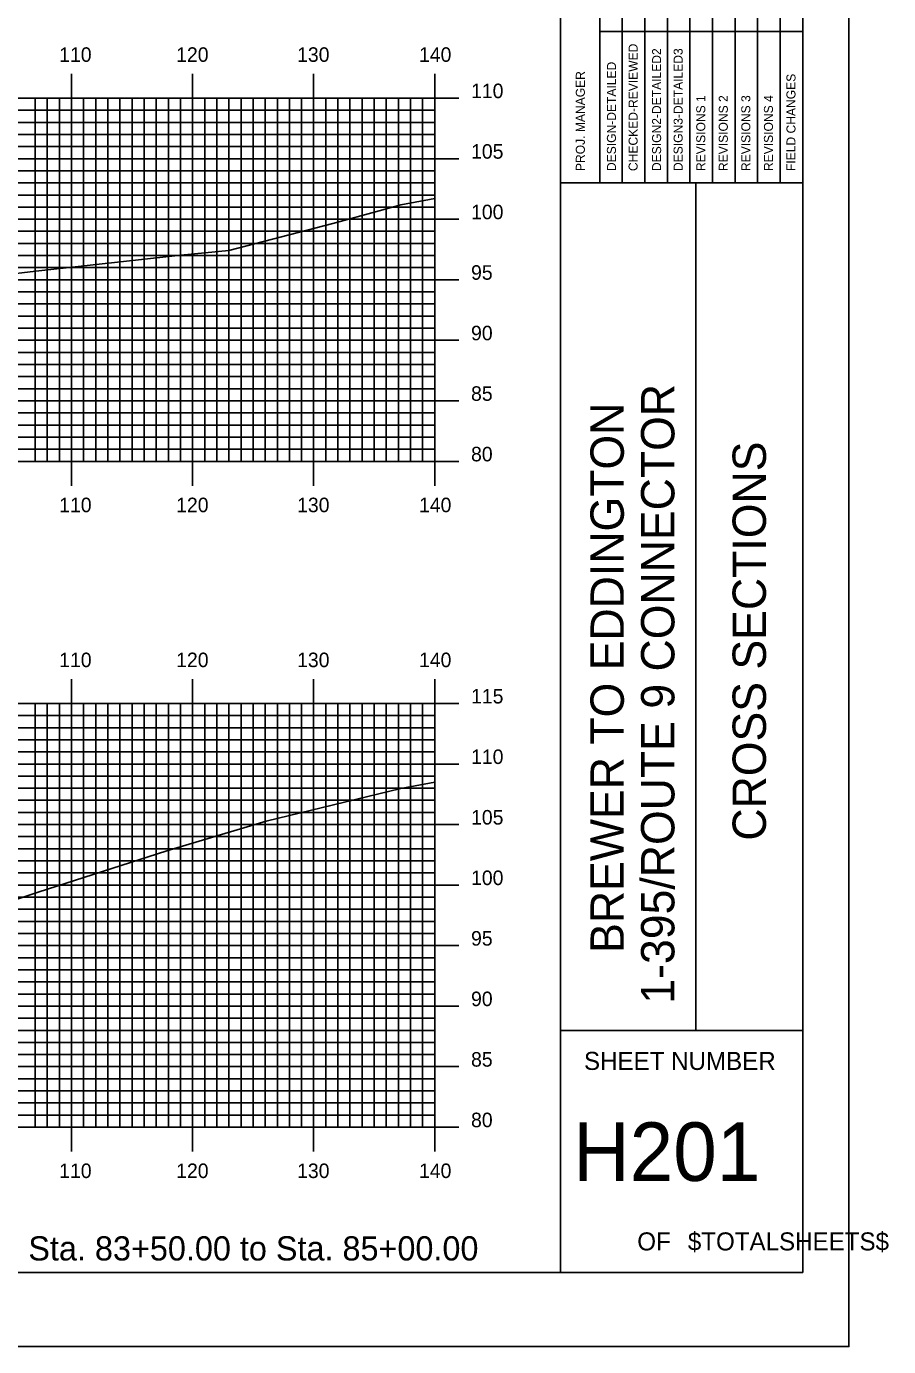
# Model space of a CAD drawing. Extents: x 1763365 to 1763708, y 442591 to 442811.
# Drawn here: x 1763637.1 to 1763708.3, y 442590.5 to 442699.6 of the extents above; entities that cross this region are included whole.
import ezdxf

# ---------------------------------------------------------------- set-up
doc = ezdxf.new("R2010")
doc.units = 0
for name, color, linetype in [('BORDER', 7, 'Continuous'), ('H_V ANNOTATION', 7, 'Continuous'), ('MAJOR', 7, 'Continuous'), ('MINOR', 7, 'Continuous'), ('PLOT BOUNDARY', 7, 'Continuous'), ('S_Roadway_Centerline', 7, 'Continuous')]:
    doc.layers.add(name, color=color, linetype=linetype)

msp = doc.modelspace()

# ---------------------------------------------------------------- linework, layer by layer
at = {"layer": 'BORDER'}
for p, q in [((1763681.21, 442596.67), (1763681.21, 442806.67)), ((1763681.21, 442686.67), (1763701.21, 442686.67)), ((1763692.39, 442616.67), (1763692.39, 442686.67)), ((1763681.21, 442616.67), (1763701.21, 442616.67))]:
    msp.add_line(p, q, dxfattribs=at)
msp.add_lwpolyline([(1763381.21, 442596.67), (1763701.21, 442596.67), (1763701.21, 442806.67), (1763381.21, 442806.67)], close=True, dxfattribs=at)
for points in [[(1763686.3, 442686.68), (1763686.3, 442721.67)], [(1763688.16, 442721.67), (1763688.16, 442686.68)], [(1763690.03, 442686.68), (1763690.03, 442721.67)], [(1763691.89, 442686.68), (1763691.89, 442721.67)], [(1763693.75, 442686.68), (1763693.75, 442721.67)], [(1763695.62, 442686.68), (1763695.62, 442721.67)], [(1763697.48, 442686.68), (1763697.48, 442721.67)], [(1763699.34, 442686.68), (1763699.34, 442721.67)], [(1763684.44, 442686.68), (1763684.44, 442720.26)], [(1763684.44, 442699.17), (1763701.21, 442699.17)]]:
    msp.add_lwpolyline(points, dxfattribs=at)
at = {"layer": 'MAJOR'}
for p, q in [((1763640.81, 442695.67), (1763640.81, 442693.67)), ((1763650.81, 442695.67), (1763650.81, 442693.67)), ((1763660.81, 442695.67), (1763660.81, 442693.67)), ((1763670.81, 442695.67), (1763670.81, 442693.67)), ((1763390.81, 442693.67), (1763670.81, 442693.67)), ((1763390.81, 442693.67), (1763670.81, 442693.67)), ((1763640.81, 442663.67), (1763640.81, 442693.67)), ((1763650.81, 442663.67), (1763650.81, 442693.67)), ((1763660.81, 442663.67), (1763660.81, 442693.67)), ((1763672.81, 442693.67), (1763668.8, 442693.67)), ((1763670.81, 442663.67), (1763670.81, 442693.67)), ((1763670.81, 442663.67), (1763670.81, 442693.67)), ((1763390.81, 442688.67), (1763670.81, 442688.67)), ((1763672.81, 442688.67), (1763668.8, 442688.67)), ((1763390.81, 442683.67), (1763670.81, 442683.67)), ((1763672.81, 442683.67), (1763668.8, 442683.67)), ((1763390.81, 442678.67), (1763670.81, 442678.67)), ((1763672.81, 442678.67), (1763668.8, 442678.67)), ((1763390.81, 442673.67), (1763670.81, 442673.67)), ((1763672.81, 442673.67), (1763668.8, 442673.67)), ((1763390.81, 442668.67), (1763670.81, 442668.67)), ((1763672.81, 442668.67), (1763668.8, 442668.67)), ((1763390.81, 442663.67), (1763670.81, 442663.67)), ((1763390.81, 442663.67), (1763670.81, 442663.67)), ((1763640.81, 442661.66), (1763640.81, 442663.67)), ((1763650.81, 442661.66), (1763650.81, 442663.67)), ((1763660.81, 442661.66), (1763660.81, 442663.67)), ((1763672.81, 442663.67), (1763668.8, 442663.67)), ((1763670.81, 442661.66), (1763670.81, 442663.67)), ((1763640.81, 442645.67), (1763640.81, 442643.67)), ((1763650.81, 442645.67), (1763650.81, 442643.67)), ((1763660.81, 442645.67), (1763660.81, 442643.67)), ((1763670.81, 442645.67), (1763670.81, 442643.67)), ((1763390.81, 442643.67), (1763670.81, 442643.67)), ((1763390.81, 442643.67), (1763670.81, 442643.67)), ((1763640.81, 442608.67), (1763640.81, 442643.67)), ((1763650.81, 442608.67), (1763650.81, 442643.67)), ((1763660.81, 442608.67), (1763660.81, 442643.67)), ((1763672.81, 442643.67), (1763668.8, 442643.67)), ((1763670.81, 442608.67), (1763670.81, 442643.67)), ((1763670.81, 442608.67), (1763670.81, 442643.67)), ((1763390.81, 442638.67), (1763670.81, 442638.67)), ((1763672.81, 442638.67), (1763668.8, 442638.67)), ((1763390.81, 442633.67), (1763670.81, 442633.67)), ((1763672.81, 442633.67), (1763668.8, 442633.67)), ((1763390.81, 442628.67), (1763670.81, 442628.67)), ((1763672.81, 442628.67), (1763668.8, 442628.67)), ((1763390.81, 442623.67), (1763670.81, 442623.67)), ((1763672.81, 442623.67), (1763668.8, 442623.67)), ((1763390.81, 442618.67), (1763670.81, 442618.67)), ((1763672.81, 442618.67), (1763668.8, 442618.67)), ((1763390.81, 442613.67), (1763670.81, 442613.67)), ((1763672.81, 442613.67), (1763668.8, 442613.67)), ((1763390.81, 442608.67), (1763670.81, 442608.67)), ((1763390.81, 442608.67), (1763670.81, 442608.67)), ((1763640.81, 442606.66), (1763640.81, 442608.67)), ((1763650.81, 442606.66), (1763650.81, 442608.67)), ((1763660.81, 442606.66), (1763660.81, 442608.67)), ((1763672.81, 442608.67), (1763668.8, 442608.67)), ((1763670.81, 442606.66), (1763670.81, 442608.67))]:
    msp.add_line(p, q, dxfattribs=at)
at = {"layer": 'MINOR'}
for p, q in [((1763637.81, 442663.67), (1763637.81, 442693.67)), ((1763638.81, 442663.67), (1763638.81, 442693.67)), ((1763639.81, 442663.67), (1763639.81, 442693.67)), ((1763641.81, 442663.67), (1763641.81, 442693.67)), ((1763642.81, 442663.67), (1763642.81, 442693.67)), ((1763643.81, 442663.67), (1763643.81, 442693.67)), ((1763644.81, 442663.67), (1763644.81, 442693.67)), ((1763645.81, 442663.67), (1763645.81, 442693.67)), ((1763646.81, 442663.67), (1763646.81, 442693.67)), ((1763647.81, 442663.67), (1763647.81, 442693.67)), ((1763648.81, 442663.67), (1763648.81, 442693.67)), ((1763649.81, 442663.67), (1763649.81, 442693.67)), ((1763651.81, 442663.67), (1763651.81, 442693.67)), ((1763652.81, 442663.67), (1763652.81, 442693.67)), ((1763653.81, 442663.67), (1763653.81, 442693.67)), ((1763654.81, 442663.67), (1763654.81, 442693.67)), ((1763655.81, 442663.67), (1763655.81, 442693.67)), ((1763656.81, 442663.67), (1763656.81, 442693.67)), ((1763657.81, 442663.67), (1763657.81, 442693.67)), ((1763658.81, 442663.67), (1763658.81, 442693.67)), ((1763659.81, 442663.67), (1763659.81, 442693.67)), ((1763661.81, 442663.67), (1763661.81, 442693.67)), ((1763662.81, 442663.67), (1763662.81, 442693.67)), ((1763663.81, 442663.67), (1763663.81, 442693.67)), ((1763664.81, 442663.67), (1763664.81, 442693.67)), ((1763665.81, 442663.67), (1763665.81, 442693.67)), ((1763666.81, 442663.67), (1763666.81, 442693.67)), ((1763667.81, 442663.67), (1763667.81, 442693.67)), ((1763668.81, 442663.67), (1763668.81, 442693.67)), ((1763669.81, 442663.67), (1763669.81, 442693.67)), ((1763390.81, 442692.67), (1763670.81, 442692.67)), ((1763390.81, 442691.67), (1763670.81, 442691.67)), ((1763670.81, 442692.67), (1763668.8, 442692.67)), ((1763670.81, 442691.67), (1763668.8, 442691.67)), ((1763390.81, 442690.67), (1763670.81, 442690.67)), ((1763670.81, 442690.67), (1763668.8, 442690.67)), ((1763390.81, 442689.67), (1763670.81, 442689.67)), ((1763670.81, 442689.67), (1763668.8, 442689.67)), ((1763390.81, 442687.67), (1763670.81, 442687.67)), ((1763670.81, 442687.67), (1763668.8, 442687.67)), ((1763390.81, 442686.67), (1763670.81, 442686.67)), ((1763670.81, 442686.67), (1763668.8, 442686.67)), ((1763390.81, 442685.67), (1763670.81, 442685.67)), ((1763670.81, 442685.67), (1763668.8, 442685.67)), ((1763390.81, 442684.67), (1763670.81, 442684.67)), ((1763670.81, 442684.67), (1763668.8, 442684.67)), ((1763390.81, 442682.67), (1763670.81, 442682.67)), ((1763670.81, 442682.67), (1763668.8, 442682.67)), ((1763390.81, 442681.67), (1763670.81, 442681.67)), ((1763670.81, 442681.67), (1763668.8, 442681.67)), ((1763390.81, 442680.67), (1763670.81, 442680.67)), ((1763390.81, 442679.67), (1763670.81, 442679.67)), ((1763670.81, 442680.67), (1763668.8, 442680.67)), ((1763670.81, 442679.67), (1763668.8, 442679.67)), ((1763390.81, 442677.67), (1763670.81, 442677.67)), ((1763670.81, 442677.67), (1763668.8, 442677.67)), ((1763390.81, 442676.67), (1763670.81, 442676.67)), ((1763670.81, 442676.67), (1763668.8, 442676.67)), ((1763390.81, 442675.67), (1763670.81, 442675.67)), ((1763670.81, 442675.67), (1763668.8, 442675.67)), ((1763390.81, 442674.67), (1763670.81, 442674.67)), ((1763670.81, 442674.67), (1763668.8, 442674.67)), ((1763390.81, 442672.67), (1763670.81, 442672.67)), ((1763670.81, 442672.67), (1763668.8, 442672.67)), ((1763390.81, 442671.67), (1763670.81, 442671.67)), ((1763670.81, 442671.67), (1763668.8, 442671.67)), ((1763390.81, 442670.67), (1763670.81, 442670.67)), ((1763670.81, 442670.67), (1763668.8, 442670.67)), ((1763390.81, 442669.67), (1763670.81, 442669.67)), ((1763670.81, 442669.67), (1763668.8, 442669.67)), ((1763390.81, 442667.67), (1763670.81, 442667.67)), ((1763670.81, 442667.67), (1763668.8, 442667.67)), ((1763390.81, 442666.67), (1763670.81, 442666.67)), ((1763670.81, 442666.67), (1763668.8, 442666.67)), ((1763390.81, 442665.67), (1763670.81, 442665.67)), ((1763670.81, 442665.67), (1763668.8, 442665.67)), ((1763390.81, 442664.67), (1763670.81, 442664.67)), ((1763670.81, 442664.67), (1763668.8, 442664.67)), ((1763637.81, 442608.67), (1763637.81, 442643.67)), ((1763638.81, 442608.67), (1763638.81, 442643.67)), ((1763639.81, 442608.67), (1763639.81, 442643.67)), ((1763641.81, 442608.67), (1763641.81, 442643.67)), ((1763642.81, 442608.67), (1763642.81, 442643.67)), ((1763643.81, 442608.67), (1763643.81, 442643.67)), ((1763644.81, 442608.67), (1763644.81, 442643.67)), ((1763645.81, 442608.67), (1763645.81, 442643.67)), ((1763646.81, 442608.67), (1763646.81, 442643.67)), ((1763647.81, 442608.67), (1763647.81, 442643.67)), ((1763648.81, 442608.67), (1763648.81, 442643.67)), ((1763649.81, 442608.67), (1763649.81, 442643.67)), ((1763651.81, 442608.67), (1763651.81, 442643.67)), ((1763652.81, 442608.67), (1763652.81, 442643.67)), ((1763653.81, 442608.67), (1763653.81, 442643.67)), ((1763654.81, 442608.67), (1763654.81, 442643.67)), ((1763655.81, 442608.67), (1763655.81, 442643.67)), ((1763656.81, 442608.67), (1763656.81, 442643.67)), ((1763657.81, 442608.67), (1763657.81, 442643.67)), ((1763658.81, 442608.67), (1763658.81, 442643.67)), ((1763659.81, 442608.67), (1763659.81, 442643.67)), ((1763661.81, 442608.67), (1763661.81, 442643.67)), ((1763662.81, 442608.67), (1763662.81, 442643.67)), ((1763663.81, 442608.67), (1763663.81, 442643.67)), ((1763664.81, 442608.67), (1763664.81, 442643.67)), ((1763665.81, 442608.67), (1763665.81, 442643.67)), ((1763666.81, 442608.67), (1763666.81, 442643.67)), ((1763667.81, 442608.67), (1763667.81, 442643.67)), ((1763668.81, 442608.67), (1763668.81, 442643.67)), ((1763669.81, 442608.67), (1763669.81, 442643.67)), ((1763390.81, 442642.67), (1763670.81, 442642.67)), ((1763670.81, 442642.67), (1763668.8, 442642.67)), ((1763390.81, 442641.67), (1763670.81, 442641.67)), ((1763670.81, 442641.67), (1763668.8, 442641.67)), ((1763390.81, 442640.67), (1763670.81, 442640.67)), ((1763670.81, 442640.67), (1763668.8, 442640.67)), ((1763390.81, 442639.67), (1763670.81, 442639.67)), ((1763670.81, 442639.67), (1763668.8, 442639.67)), ((1763390.81, 442637.67), (1763670.81, 442637.67)), ((1763670.81, 442637.67), (1763668.8, 442637.67)), ((1763390.81, 442636.67), (1763670.81, 442636.67)), ((1763670.81, 442636.67), (1763668.8, 442636.67)), ((1763390.81, 442635.67), (1763670.81, 442635.67)), ((1763670.81, 442635.67), (1763668.8, 442635.67)), ((1763390.81, 442634.67), (1763670.81, 442634.67)), ((1763670.81, 442634.67), (1763668.8, 442634.67)), ((1763390.81, 442632.67), (1763670.81, 442632.67)), ((1763670.81, 442632.67), (1763668.8, 442632.67)), ((1763390.81, 442631.67), (1763670.81, 442631.67)), ((1763390.81, 442630.67), (1763670.81, 442630.67)), ((1763670.81, 442631.67), (1763668.8, 442631.67)), ((1763670.81, 442630.67), (1763668.8, 442630.67)), ((1763390.81, 442629.67), (1763670.81, 442629.67)), ((1763670.81, 442629.67), (1763668.8, 442629.67)), ((1763390.81, 442627.67), (1763670.81, 442627.67)), ((1763670.81, 442627.67), (1763668.8, 442627.67)), ((1763390.81, 442626.67), (1763670.81, 442626.67)), ((1763670.81, 442626.67), (1763668.8, 442626.67)), ((1763390.81, 442625.67), (1763670.81, 442625.67)), ((1763670.81, 442625.67), (1763668.8, 442625.67)), ((1763390.81, 442624.67), (1763670.81, 442624.67)), ((1763670.81, 442624.67), (1763668.8, 442624.67)), ((1763390.81, 442622.67), (1763670.81, 442622.67)), ((1763670.81, 442622.67), (1763668.8, 442622.67)), ((1763390.81, 442621.67), (1763670.81, 442621.67)), ((1763670.81, 442621.67), (1763668.8, 442621.67)), ((1763390.81, 442620.67), (1763670.81, 442620.67)), ((1763670.81, 442620.67), (1763668.8, 442620.67)), ((1763390.81, 442619.67), (1763670.81, 442619.67)), ((1763670.81, 442619.67), (1763668.8, 442619.67)), ((1763390.81, 442617.67), (1763670.81, 442617.67)), ((1763670.81, 442617.67), (1763668.8, 442617.67)), ((1763390.81, 442616.67), (1763670.81, 442616.67)), ((1763670.81, 442616.67), (1763668.8, 442616.67)), ((1763390.81, 442615.67), (1763670.81, 442615.67)), ((1763670.81, 442615.67), (1763668.8, 442615.67)), ((1763390.81, 442614.67), (1763670.81, 442614.67)), ((1763670.81, 442614.67), (1763668.8, 442614.67)), ((1763390.81, 442612.67), (1763670.81, 442612.67)), ((1763670.81, 442612.67), (1763668.8, 442612.67)), ((1763390.81, 442611.67), (1763670.81, 442611.67)), ((1763670.81, 442611.67), (1763668.8, 442611.67)), ((1763390.81, 442610.67), (1763670.81, 442610.67)), ((1763670.81, 442610.67), (1763668.8, 442610.67)), ((1763390.81, 442609.67), (1763670.81, 442609.67)), ((1763670.81, 442609.67), (1763668.8, 442609.67))]:
    msp.add_line(p, q, dxfattribs=at)
at = {"layer": 'PLOT BOUNDARY'}
msp.add_lwpolyline([(1763365.02, 442590.55), (1763705.02, 442590.55), (1763705.02, 442810.55), (1763365.02, 442810.55)], close=True, dxfattribs=at)
at = {"layer": 'S_Roadway_Centerline'}
for points in [[(1763581.46, 442676.29), (1763588.6, 442676.71), (1763592.96, 442676.91), (1763595.12, 442677.08), (1763601.47, 442677.26), (1763618.94, 442677.86), (1763627.63, 442678.34), (1763632.26, 442678.72), (1763637.85, 442679.39), (1763649.83, 442680.7), (1763653.8, 442681.08), (1763662.38, 442683.31), (1763666.22, 442684.37), (1763668.01, 442684.87), (1763670.81, 442685.38)], [(1763584.37, 442621.6), (1763595.43, 442622.5), (1763602.3, 442622.86), (1763612.81, 442623.1), (1763620.21, 442623.98), (1763631.45, 442626.15), (1763635.5, 442627.24), (1763638.05, 442628.07), (1763648.67, 442631.5), (1763656.9, 442633.95), (1763668.02, 442636.65), (1763670.81, 442637.18)]]:
    msp.add_lwpolyline(points, dxfattribs=at)

# ---------------------------------------------------------------- texts
at = {"layer": 'BORDER'}
for s, height, p in [('CHECKED-REVIEWED', 0.7455, (1763687.57, 442687.65)), ('DESIGN2-DETAILED2', 0.7455, (1763689.51, 442687.65)), ('DESIGN3-DETAILED3', 0.7455, (1763691.29, 442687.65)), ('DESIGN-DETAILED', 0.7455, (1763685.78, 442687.65)), ('PROJ. MANAGER', 0.7455, (1763683.21, 442687.65)), ('FIELD CHANGES', 0.7455, (1763700.61, 442687.65)), ('REVISIONS 1', 0.7455, (1763693.16, 442687.65)), ('REVISIONS 2', 0.7455, (1763695.02, 442687.65)), ('REVISIONS 3', 0.7455, (1763696.88, 442687.65)), ('REVISIONS 4', 0.7455, (1763698.75, 442687.65)), ('1-395/ROUTE 9 CONNECTOR', 2.7557, (1763690.61, 442618.87)), ('BREWER TO EDDINGTON', 2.7557, (1763686.43, 442623.07)), ('CROSS SECTIONS', 2.7557, (1763698.17, 442632.34))]:
    msp.add_text(s, height=height, rotation=90, dxfattribs=at).set_placement(p)
for s, height, p in [('SHEET NUMBER', 1.4905, (1763683.14, 442613.4)), ('H201', 4.839, (1763682.24, 442604.23)), ('$TOTALSHEETS$', 1.4905, (1763691.72, 442598.49)), ('OF', 1.491, (1763687.54, 442598.49))]:
    msp.add_text(s, height=height, dxfattribs=at).set_placement(p)
at = {"layer": 'H_V ANNOTATION'}
for s, height, p in [('110', 1.2, (1763639.79, 442696.67)), ('120', 1.2, (1763649.45, 442696.67)), ('130', 1.2, (1763659.44, 442696.67)), ('140', 1.2, (1763669.51, 442696.67)), ('110', 1.2, (1763673.81, 442693.67)), ('105', 1.2, (1763673.81, 442688.67)), ('100', 1.2, (1763673.81, 442683.67)), ('95', 1.2, (1763673.81, 442678.67)), ('90', 1.2, (1763673.81, 442673.67)), ('85', 1.2, (1763673.81, 442668.67)), ('80', 1.2, (1763673.81, 442663.67)), ('110', 1.2, (1763639.79, 442659.47)), ('120', 1.2, (1763649.45, 442659.47)), ('130', 1.2, (1763659.44, 442659.47)), ('140', 1.2, (1763669.51, 442659.47)), ('110', 1.2, (1763639.79, 442646.67)), ('120', 1.2, (1763649.45, 442646.67)), ('130', 1.2, (1763659.44, 442646.67)), ('140', 1.2, (1763669.51, 442646.67)), ('115', 1.2, (1763673.81, 442643.67)), ('110', 1.2, (1763673.81, 442638.67)), ('105', 1.2, (1763673.81, 442633.67)), ('100', 1.2, (1763673.81, 442628.67)), ('95', 1.2, (1763673.81, 442623.67)), ('90', 1.2, (1763673.81, 442618.67)), ('85', 1.2, (1763673.81, 442613.67)), ('80', 1.2, (1763673.81, 442608.67)), ('110', 1.2, (1763639.79, 442604.47)), ('120', 1.2, (1763649.45, 442604.47)), ('130', 1.2, (1763659.44, 442604.47)), ('140', 1.2, (1763669.51, 442604.47)), ('Sta. 83+50.00 to Sta. 85+00.00', 2.0004, (1763637.24, 442597.66))]:
    msp.add_text(s, height=height, dxfattribs=at).set_placement(p)

doc.saveas('drawing.dxf')
